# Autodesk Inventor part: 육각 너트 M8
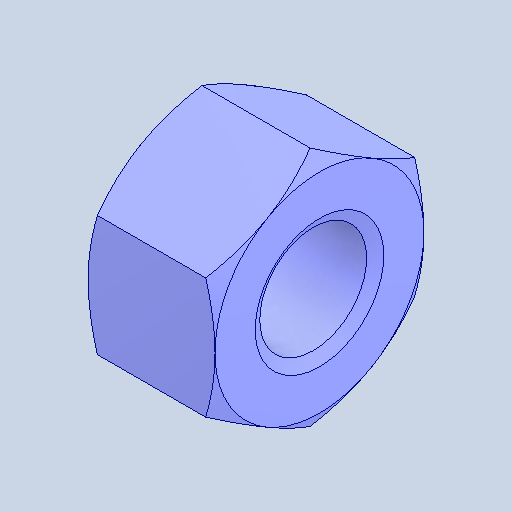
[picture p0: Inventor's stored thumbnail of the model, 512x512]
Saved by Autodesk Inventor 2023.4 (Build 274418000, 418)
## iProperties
Created: 2024-11
Part Number: 육각 너트 M8
Material: 강철, 연강
Description: 6각 너트 및 6각 가는 너트
Document SubType Name: Modeling
Designer: EDU
Density: 7.85 g/cm^3
Appearance: 기본값
Author: jhkim
Sending System: Autodesk Inventor 2025
Preprocessor: ST-DEVELOPER v20
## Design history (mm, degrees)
feature "Solid1"
node "솔리드1"
